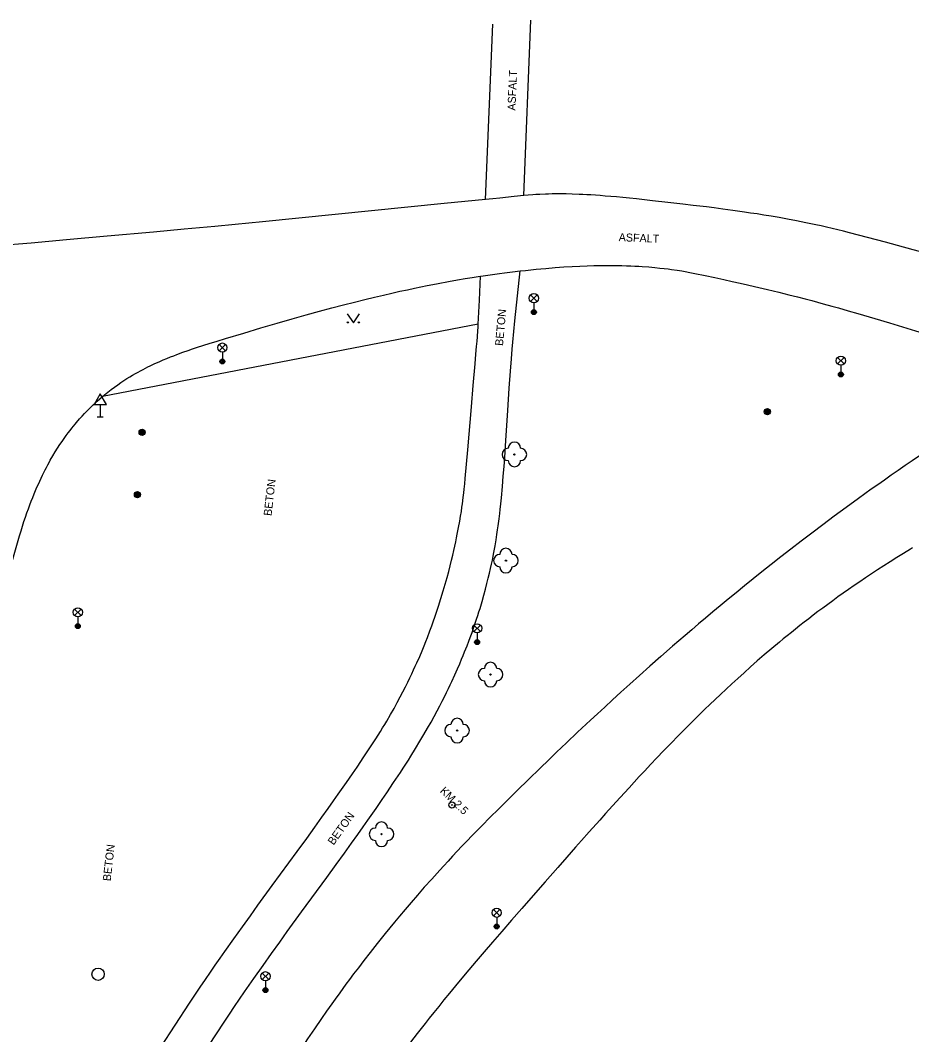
# Model space of a CAD drawing. Extents: x -541281 to -539153, y -1183881 to -1182141.
# Drawn here: x -539853.2 to -539780.8, y -1183251.4 to -1183169.1 of the extents above; entities that cross this region are included whole.
import ezdxf

# ---------------------------------------------------------------- set-up
doc = ezdxf.new("R2010")
doc.units = 0
for name, color, linetype in [('Vrstva 10', 7, 'Continuous'), ('Vrstva 11', 7, 'Continuous'), ('Vrstva 13', 7, 'Continuous'), ('Vrstva 22', 7, 'Continuous'), ('Vrstva 25', 7, 'Continuous'), ('Vrstva 27', 7, 'Continuous'), ('Vrstva 33', 7, 'Continuous'), ('Vrstva 34', 7, 'Continuous'), ('Vrstva 36', 7, 'Continuous'), ('Vrstva 40', 7, 'Continuous')]:
    doc.layers.add(name, color=color, linetype=linetype)

msp = doc.modelspace()

# ---------------------------------------------------------------- linework, layer by layer
at = {"layer": 'Vrstva 10'}
for p, q in [((-539818.798, -1183183.975), (-539830.587, -1183185.158)), ((-539815.43, -1183183.64), (-539818.798, -1183183.975)), ((-539795.35, -1183184.53), (-539796.163, -1183184.42)), ((-539852.324, -1183187.172), (-539857.371, -1183187.609)), ((-539849.441, -1183186.921), (-539852.324, -1183187.172)), ((-539813.254, -1183189.513), (-539812.62, -1183189.44)), ((-539786, -1183192.67), (-539785.21, -1183192.9)), ((-539792.209, -1183220.104), (-539792.806, -1183220.612)), ((-539799.777, -1183227.166), (-539800.402, -1183227.806)), ((-539814.125, -1183243.071), (-539814.863, -1183243.926)), ((-539820.984, -1183251.348), (-539821.54, -1183252.067))]:
    msp.add_line(p, q, dxfattribs=at)
for points in [[(-539808.407, -1183183.203), (-539808.9, -1183183.192), (-539809.331, -1183183.188), (-539809.707, -1183183.189), (-539810.037, -1183183.192), (-539810.325, -1183183.198), (-539810.578, -1183183.206), (-539811.019, -1183183.224), (-539811.349, -1183183.242), (-539811.597, -1183183.258), (-539811.969, -1183183.286), (-539812.34, -1183183.32), (-539813.113, -1183183.398), (-539814.271, -1183183.521), (-539814.85, -1183183.581), (-539815.43, -1183183.64)], [(-539806.516, -1183183.296), (-539806.881, -1183183.273), (-539807.223, -1183183.253), (-539807.544, -1183183.236), (-539807.844, -1183183.223), (-539808.407, -1183183.203)], [(-539805.713, -1183183.357), (-539806.127, -1183183.324), (-539806.516, -1183183.296)], [(-539796.163, -1183184.42), (-539796.876, -1183184.327), (-539797.5, -1183184.248), (-539798.594, -1183184.114), (-539799.415, -1183184.018), (-539800.647, -1183183.877), (-539801.88, -1183183.74), (-539803.186, -1183183.598), (-539803.758, -1183183.538), (-539804.295, -1183183.484), (-539804.798, -1183183.436), (-539805.27, -1183183.394), (-539805.713, -1183183.357)], [(-539785.88, -1183186.34), (-539786.372, -1183186.214), (-539786.849, -1183186.096), (-539787.312, -1183185.986), (-539787.761, -1183185.882), (-539788.196, -1183185.784), (-539788.619, -1183185.692), (-539789.028, -1183185.606), (-539789.426, -1183185.524), (-539790.196, -1183185.372), (-539790.92, -1183185.236), (-539791.6, -1183185.114), (-539792.238, -1183185.005), (-539792.836, -1183184.906), (-539793.398, -1183184.817), (-539793.926, -1183184.736), (-539794.421, -1183184.663), (-539795.35, -1183184.53)], [(-539830.587, -1183185.158), (-539833.534, -1183185.45), (-539835.745, -1183185.665), (-539837.403, -1183185.825), (-539839.891, -1183186.06)], [(-539839.891, -1183186.06), (-539842.38, -1183186.29), (-539846.145, -1183186.629), (-539849.441, -1183186.921)], [(-539782.971, -1183187.108), (-539784.425, -1183186.721), (-539785.88, -1183186.34)], [(-539773.666, -1183189.666), (-539776.712, -1183188.818), (-539778.998, -1183188.187), (-539780.715, -1183187.717), (-539782.004, -1183187.368), (-539782.971, -1183187.108)], [(-539812.62, -1183189.44), (-539812.18, -1183189.392), (-539811.752, -1183189.347), (-539811.338, -1183189.305), (-539810.935, -1183189.267), (-539810.545, -1183189.232), (-539809.787, -1183189.169), (-539809.076, -1183189.117), (-539808.408, -1183189.076), (-539807.781, -1183189.044), (-539807.193, -1183189.021), (-539806.642, -1183189.005), (-539806.125, -1183188.995), (-539805.64, -1183188.99), (-539805.186, -1183188.991), (-539804.761, -1183188.996)], [(-539804.761, -1183188.996), (-539804.362, -1183189.004), (-539803.989, -1183189.015), (-539803.639, -1183189.028), (-539803.311, -1183189.044), (-539803.004, -1183189.061), (-539802.716, -1183189.079), (-539802.177, -1183189.119), (-539801.707, -1183189.16), (-539801.295, -1183189.202), (-539800.936, -1183189.242), (-539800.623, -1183189.281), (-539800.348, -1183189.317), (-539799.869, -1183189.387), (-539799.511, -1183189.443), (-539799.243, -1183189.489), (-539798.841, -1183189.562), (-539798.44, -1183189.64), (-539797.605, -1183189.812), (-539796.823, -1183189.976), (-539796.091, -1183190.134), (-539795.405, -1183190.284)], [(-539823.033, -1183191.24), (-539822.388, -1183191.095), (-539821.782, -1183190.963), (-539821.214, -1183190.842), (-539820.681, -1183190.732), (-539820.181, -1183190.631), (-539819.712, -1183190.538), (-539819.271, -1183190.453), (-539818.445, -1183190.3), (-539817.721, -1183190.171), (-539817.086, -1183190.064), (-539816.53, -1183189.973), (-539816.043, -1183189.896), (-539815.846, -1183189.866), (-539815.617, -1183189.832), (-539814.87, -1183189.724), (-539814.308, -1183189.647), (-539813.887, -1183189.592), (-539813.254, -1183189.513)], [(-539795.405, -1183190.284), (-539794.763, -1183190.428), (-539794.162, -1183190.564), (-539793.599, -1183190.695), (-539792.544, -1183190.945), (-539791.623, -1183191.169), (-539790.818, -1183191.37), (-539790.114, -1183191.549), (-539789.499, -1183191.709), (-539788.962, -1183191.85), (-539788.022, -1183192.103), (-539787.318, -1183192.297), (-539786.79, -1183192.445), (-539786, -1183192.67)], [(-539833.668, -1183194.064), (-539832.361, -1183193.682), (-539831.137, -1183193.331), (-539829.989, -1183193.008), (-539828.913, -1183192.712), (-539827.904, -1183192.442), (-539826.957, -1183192.194), (-539826.069, -1183191.967), (-539825.236, -1183191.76), (-539824.454, -1183191.571)], [(-539824.454, -1183191.571), (-539823.721, -1183191.398), (-539823.033, -1183191.24)], [(-539785.21, -1183192.9), (-539783.839, -1183193.305), (-539782.64, -1183193.661), (-539780.547, -1183194.29), (-539778.979, -1183194.766), (-539777.803, -1183195.126), (-539776.041, -1183195.67)], [(-539842.838, -1183197.23), (-539842.65, -1183197.138), (-539842.284, -1183196.965), (-539841.939, -1183196.81), (-539841.614, -1183196.669), (-539841.307, -1183196.541), (-539841.019, -1183196.425), (-539840.747, -1183196.319), (-539840.491, -1183196.222), (-539840.009, -1183196.045), (-539839.585, -1183195.896), (-539839.212, -1183195.769), (-539838.884, -1183195.66), (-539838.306, -1183195.473), (-539837.87, -1183195.336), (-539837.213, -1183195.132), (-539836.55, -1183194.93), (-539835.062, -1183194.48), (-539833.668, -1183194.064)], [(-539850.169, -1183203.826), (-539849.984, -1183203.542), (-539849.806, -1183203.278), (-539849.635, -1183203.033), (-539849.471, -1183202.805), (-539849.314, -1183202.593), (-539849.163, -1183202.396), (-539849.019, -1183202.213), (-539848.882, -1183202.042), (-539848.751, -1183201.883), (-539848.626, -1183201.735), (-539848.388, -1183201.459), (-539848.173, -1183201.221), (-539847.981, -1183201.015), (-539847.81, -1183200.836), (-539847.658, -1183200.681), (-539847.522, -1183200.546), (-539847.281, -1183200.313), (-539847.096, -1183200.139), (-539846.955, -1183200.011), (-539846.739, -1183199.819), (-539846.52, -1183199.63), (-539846.377, -1183199.51), (-539846.236, -1183199.394), (-539846.097, -1183199.283), (-539845.822, -1183199.068), (-539845.553, -1183198.868), (-539845.292, -1183198.68), (-539845.037, -1183198.504), (-539844.789, -1183198.34), (-539844.548, -1183198.185), (-539844.313, -1183198.039), (-539844.084, -1183197.902), (-539843.862, -1183197.774), (-539843.645, -1183197.652), (-539843.435, -1183197.537), (-539843.23, -1183197.429), (-539843.031, -1183197.327), (-539842.838, -1183197.23)], [(-539852.902, -1183209.788), (-539852.783, -1183209.431), (-539852.664, -1183209.086), (-539852.546, -1183208.755), (-539852.428, -1183208.435), (-539852.311, -1183208.126), (-539852.194, -1183207.829), (-539852.078, -1183207.542), (-539851.963, -1183207.266), (-539851.848, -1183207), (-539851.735, -1183206.744), (-539851.622, -1183206.496), (-539851.51, -1183206.258), (-539851.4, -1183206.028), (-539851.291, -1183205.807), (-539851.182, -1183205.594), (-539851.076, -1183205.388), (-539850.97, -1183205.19), (-539850.866, -1183204.999), (-539850.763, -1183204.815), (-539850.559, -1183204.46), (-539850.361, -1183204.131), (-539850.169, -1183203.826)], [(-539855.674, -1183219.912), (-539855.544, -1183219.349), (-539855.419, -1183218.822), (-539855.298, -1183218.328), (-539855.184, -1183217.865), (-539854.962, -1183216.999), (-539854.763, -1183216.241), (-539854.585, -1183215.579), (-539854.426, -1183214.999), (-539854.143, -1183213.985), (-539853.926, -1183213.224), (-539853.596, -1183212.083), (-539853.26, -1183210.94), (-539853.14, -1183210.542)], [(-539853.14, -1183210.542), (-539853.021, -1183210.158), (-539852.902, -1183209.788)], [(-539780.767, -1183211.929), (-539780.94, -1183212.03), (-539781.504, -1183212.371), (-539782.052, -1183212.709), (-539782.587, -1183213.044), (-539783.108, -1183213.376), (-539783.616, -1183213.704), (-539784.111, -1183214.029), (-539784.594, -1183214.351)], [(-539784.594, -1183214.351), (-539785.065, -1183214.67), (-539785.525, -1183214.985), (-539785.974, -1183215.297), (-539786.411, -1183215.606), (-539786.839, -1183215.912), (-539787.256, -1183216.214), (-539787.664, -1183216.513), (-539788.062, -1183216.808), (-539788.451, -1183217.1), (-539788.832, -1183217.389), (-539789.203, -1183217.675), (-539789.567, -1183217.958), (-539789.922, -1183218.237), (-539790.27, -1183218.513), (-539790.61, -1183218.785), (-539790.943, -1183219.054), (-539791.268, -1183219.321), (-539791.587, -1183219.584), (-539792.209, -1183220.104)], [(-539792.806, -1183220.612), (-539793.378, -1183221.106), (-539793.927, -1183221.589), (-539794.455, -1183222.059), (-539794.961, -1183222.517), (-539795.449, -1183222.963), (-539795.917, -1183223.397), (-539796.368, -1183223.82), (-539796.802, -1183224.232), (-539797.22, -1183224.632), (-539797.623, -1183225.022), (-539798.011, -1183225.401), (-539798.386, -1183225.77), (-539799.107, -1183226.488), (-539799.777, -1183227.166)], [(-539800.402, -1183227.806), (-539800.984, -1183228.41), (-539801.527, -1183228.979)], [(-539801.527, -1183228.979), (-539802.035, -1183229.515), (-539802.509, -1183230.02), (-539802.952, -1183230.496), (-539803.781, -1183231.393), (-539804.503, -1183232.184), (-539805.134, -1183232.88), (-539805.686, -1183233.492), (-539806.169, -1183234.031), (-539807.014, -1183234.978), (-539807.648, -1183235.693), (-539808.125, -1183236.232)], [(-539808.125, -1183236.232), (-539808.841, -1183237.043), (-539809.56, -1183237.86), (-539810.602, -1183239.045), (-539811.576, -1183240.152), (-539812.485, -1183241.189), (-539813.333, -1183242.16), (-539814.125, -1183243.071)], [(-539814.863, -1183243.926), (-539815.552, -1183244.728), (-539816.194, -1183245.482), (-539816.793, -1183246.191), (-539817.352, -1183246.857), (-539817.873, -1183247.483), (-539818.359, -1183248.072), (-539818.813, -1183248.626), (-539819.236, -1183249.147), (-539819.631, -1183249.637), (-539819.999, -1183250.098), (-539820.343, -1183250.532), (-539820.984, -1183251.348)]]:
    msp.add_lwpolyline(points, dxfattribs=at)
at = {"layer": 'Vrstva 11'}
for p, q in [((-539812.34, -1183183.32), (-539811.75, -1183169.09)), ((-539815.43, -1183183.64), (-539814.84, -1183169.41)), ((-539815.938, -1183191.818), (-539815.846, -1183189.866)), ((-539816.03, -1183193.77), (-539846.52, -1183199.63)), ((-539813.508, -1183198.951), (-539813.411, -1183197.587)), ((-539814.186, -1183208.336), (-539814.14, -1183207.85)), ((-539816.269, -1183218.037), (-539816.165, -1183217.724)), ((-539821.575, -1183222.48), (-539821.416, -1183222.148)), ((-539826.312, -1183235.908), (-539825.807, -1183235.198)), ((-539839.46, -1183248.9), (-539839.021, -1183248.235))]:
    msp.add_line(p, q, dxfattribs=at)
for points in [[(-539813.411, -1183197.587), (-539813.332, -1183196.564), (-539813.268, -1183195.798), (-539813.218, -1183195.223), (-539813.137, -1183194.361), (-539813.05, -1183193.5), (-539812.835, -1183191.47), (-539812.62, -1183189.44)], [(-539816.043, -1183194.025), (-539816.03, -1183193.77), (-539815.938, -1183191.818)], [(-539816.878, -1183203.973), (-539816.58, -1183200.482), (-539816.434, -1183198.736), (-539816.29, -1183196.99), (-539816.22, -1183196.185), (-539816.164, -1183195.582), (-539816.124, -1183195.129), (-539816.096, -1183194.79), (-539816.059, -1183194.28), (-539816.043, -1183194.025)], [(-539814.14, -1183207.85), (-539814.062, -1183206.953), (-539813.994, -1183206.113), (-539813.934, -1183205.324), (-539813.881, -1183204.585), (-539813.786, -1183203.198), (-539813.629, -1183200.771), (-539813.508, -1183198.951)], [(-539818.193, -1183212.933), (-539818.094, -1183212.522), (-539818.005, -1183212.137), (-539817.925, -1183211.776), (-539817.852, -1183211.437), (-539817.786, -1183211.118), (-539817.726, -1183210.82), (-539817.619, -1183210.259), (-539817.531, -1183209.767), (-539817.459, -1183209.336), (-539817.4, -1183208.958), (-539817.35, -1183208.628), (-539817.309, -1183208.338), (-539817.243, -1183207.83), (-539817.197, -1183207.448), (-539817.164, -1183207.162), (-539817.12, -1183206.731), (-539817.08, -1183206.3), (-539816.878, -1183203.973)], [(-539816.165, -1183217.724), (-539816.066, -1183217.421), (-539815.973, -1183217.126), (-539815.884, -1183216.841), (-539815.719, -1183216.287), (-539815.571, -1183215.767), (-539815.439, -1183215.279), (-539815.32, -1183214.82), (-539815.213, -1183214.389), (-539815.117, -1183213.985), (-539815.031, -1183213.605), (-539814.953, -1183213.249), (-539814.883, -1183212.915), (-539814.82, -1183212.601), (-539814.763, -1183212.306), (-539814.661, -1183211.753), (-539814.577, -1183211.268), (-539814.508, -1183210.843), (-539814.452, -1183210.471), (-539814.405, -1183210.145), (-539814.328, -1183209.573), (-539814.275, -1183209.143), (-539814.238, -1183208.82), (-539814.186, -1183208.336)], [(-539821.416, -1183222.148), (-539821.27, -1183221.835), (-539821.135, -1183221.54), (-539821.011, -1183221.263), (-539820.782, -1183220.741), (-539820.587, -1183220.282), (-539820.42, -1183219.877), (-539820.277, -1183219.522), (-539820.155, -1183219.21), (-539819.946, -1183218.66), (-539819.794, -1183218.246), (-539819.682, -1183217.934), (-539819.518, -1183217.463), (-539819.36, -1183216.99), (-539819.253, -1183216.661), (-539819.051, -1183216.022), (-539818.869, -1183215.423), (-539818.705, -1183214.86), (-539818.557, -1183214.331), (-539818.423, -1183213.835), (-539818.302, -1183213.37), (-539818.193, -1183212.933)], [(-539820.436, -1183227.071), (-539820.137, -1183226.552), (-539819.862, -1183226.063), (-539819.609, -1183225.601), (-539819.375, -1183225.167), (-539819.159, -1183224.758), (-539818.961, -1183224.373), (-539818.777, -1183224.01), (-539818.607, -1183223.668), (-539818.451, -1183223.347), (-539818.306, -1183223.044), (-539818.172, -1183222.76), (-539817.925, -1183222.223), (-539817.714, -1183221.751), (-539817.534, -1183221.335), (-539817.379, -1183220.97), (-539817.246, -1183220.649), (-539817.131, -1183220.366), (-539816.935, -1183219.87), (-539816.792, -1183219.495), (-539816.686, -1183219.213), (-539816.531, -1183218.788), (-539816.38, -1183218.36), (-539816.269, -1183218.037)], [(-539822.136, -1183223.606), (-539821.933, -1183223.208), (-539821.747, -1183222.833), (-539821.575, -1183222.48)], [(-539827.387, -1183231.93), (-539826.721, -1183230.976), (-539826.225, -1183230.257), (-539825.856, -1183229.715), (-539825.305, -1183228.9), (-539824.76, -1183228.08), (-539824.548, -1183227.756), (-539824.345, -1183227.44), (-539824.151, -1183227.134), (-539823.965, -1183226.835), (-539823.787, -1183226.545), (-539823.616, -1183226.263), (-539823.453, -1183225.989), (-539823.143, -1183225.455), (-539822.858, -1183224.952), (-539822.597, -1183224.476), (-539822.357, -1183224.028), (-539822.136, -1183223.606)], [(-539825.807, -1183235.198), (-539825.366, -1183234.576), (-539824.982, -1183234.03), (-539824.314, -1183233.071), (-539823.817, -1183232.349), (-539823.447, -1183231.805), (-539822.896, -1183230.985), (-539822.35, -1183230.16), (-539822.123, -1183229.812), (-539821.905, -1183229.474), (-539821.696, -1183229.146), (-539821.496, -1183228.827), (-539821.113, -1183228.207), (-539820.76, -1183227.622), (-539820.436, -1183227.071)], [(-539828.209, -1183233.092), (-539827.77, -1183232.473), (-539827.387, -1183231.93)], [(-539833.907, -1183240.938), (-539832.748, -1183239.348), (-539830.715, -1183236.566), (-539829.954, -1183235.52), (-539829.291, -1183234.603), (-539828.713, -1183233.798), (-539828.209, -1183233.092)], [(-539827.559, -1183237.637), (-539826.893, -1183236.716), (-539826.312, -1183235.908)], [(-539832.801, -1183244.847), (-539832.145, -1183243.934), (-539831.527, -1183243.08), (-539830.364, -1183241.482), (-539828.323, -1183238.687), (-539827.559, -1183237.637)], [(-539839.021, -1183248.235), (-539838.593, -1183247.594), (-539838.175, -1183246.976), (-539837.767, -1183246.378), (-539837.37, -1183245.802), (-539836.982, -1183245.245), (-539836.605, -1183244.706), (-539835.87, -1183243.667), (-539835.176, -1183242.695), (-539834.522, -1183241.787), (-539833.907, -1183240.938)], [(-539834.233, -1183246.872), (-539833.497, -1183245.825), (-539832.801, -1183244.847)], [(-539839.117, -1183254.196), (-539837.886, -1183252.313), (-539836.65, -1183250.43), (-539836.222, -1183249.783), (-539835.804, -1183249.159), (-539835.396, -1183248.557), (-539834.998, -1183247.975), (-539834.611, -1183247.414), (-539834.233, -1183246.872)], [(-539844.807, -1183257.195), (-539844.147, -1183256.153), (-539843.568, -1183255.242), (-539842.549, -1183253.652), (-539841.781, -1183252.461), (-539840.623, -1183250.679), (-539839.46, -1183248.9)]]:
    msp.add_lwpolyline(points, dxfattribs=at)
at = {"layer": 'Vrstva 13'}
msp.add_line((-539802.936, -1183222.28), (-539803.716, -1183222.981), dxfattribs=at)
for points in [[(-539778.983, -1183203.634), (-539779.599, -1183204.044), (-539780.204, -1183204.45), (-539780.797, -1183204.851), (-539781.38, -1183205.248), (-539781.951, -1183205.641), (-539782.512, -1183206.03), (-539783.062, -1183206.414), (-539783.602, -1183206.794), (-539784.132, -1183207.17), (-539784.653, -1183207.542), (-539785.164, -1183207.91), (-539786.166, -1183208.638), (-539787.132, -1183209.349)], [(-539787.132, -1183209.349), (-539788.063, -1183210.043), (-539788.961, -1183210.72), (-539789.827, -1183211.381), (-539790.663, -1183212.025), (-539791.469, -1183212.654), (-539792.246, -1183213.266), (-539792.997, -1183213.863), (-539793.722, -1183214.444), (-539794.422, -1183215.01)], [(-539794.422, -1183215.01), (-539795.097, -1183215.561), (-539795.75, -1183216.098)], [(-539795.75, -1183216.098), (-539796.38, -1183216.62), (-539796.989, -1183217.128), (-539797.577, -1183217.622), (-539798.145, -1183218.103), (-539798.695, -1183218.571), (-539799.226, -1183219.026), (-539800.25, -1183219.912), (-539801.207, -1183220.748), (-539802.101, -1183221.536), (-539802.936, -1183222.28)], [(-539803.716, -1183222.981), (-539804.445, -1183223.641), (-539805.126, -1183224.263), (-539805.764, -1183224.848), (-539806.36, -1183225.399)], [(-539806.36, -1183225.399), (-539806.918, -1183225.918), (-539807.961, -1183226.895), (-539808.87, -1183227.754), (-539809.663, -1183228.51), (-539810.355, -1183229.175), (-539810.96, -1183229.758), (-539812.015, -1183230.785), (-539812.804, -1183231.558), (-539813.394, -1183232.141)], [(-539813.394, -1183232.141), (-539814.278, -1183233.018), (-539815.16, -1183233.9), (-539815.632, -1183234.376), (-539816.086, -1183234.838), (-539816.522, -1183235.287), (-539816.943, -1183235.723), (-539817.348, -1183236.148), (-539817.738, -1183236.56), (-539818.113, -1183236.96), (-539818.475, -1183237.349), (-539818.823, -1183237.727), (-539819.159, -1183238.094), (-539819.805, -1183238.809)], [(-539819.805, -1183238.809), (-539820.405, -1183239.483), (-539820.962, -1183240.118)], [(-539820.962, -1183240.118), (-539821.479, -1183240.717), (-539821.961, -1183241.281), (-539822.409, -1183241.813), (-539822.826, -1183242.313), (-539823.214, -1183242.785), (-539823.576, -1183243.229), (-539823.913, -1183243.647), (-539824.228, -1183244.04), (-539824.813, -1183244.782), (-539825.32, -1183245.436), (-539825.76, -1183246.012), (-539826.143, -1183246.518), (-539826.475, -1183246.963), (-539826.765, -1183247.354)], [(-539826.765, -1183247.354), (-539827.268, -1183248.043), (-539827.642, -1183248.563)], [(-539827.642, -1183248.563), (-539827.921, -1183248.955), (-539828.337, -1183249.545), (-539828.75, -1183250.14), (-539829.327, -1183250.98), (-539829.881, -1183251.795), (-539830.414, -1183252.585), (-539830.927, -1183253.352), (-539831.42, -1183254.096), (-539831.895, -1183254.818), (-539832.352, -1183255.518), (-539832.791, -1183256.198), (-539833.215, -1183256.857)]]:
    msp.add_lwpolyline(points, dxfattribs=at)
at = {"layer": 'Vrstva 22'}
for centre in [(-539813.09, -1183204.34), (-539813.78, -1183212.96), (-539815.03, -1183222.21), (-539817.74, -1183226.76), (-539823.88, -1183235.17)]:
    msp.add_circle(centre, 0.05, dxfattribs=at)
for centre, start, end in [((-539813.59, -1183204.34), 89.99973, 269.99973), ((-539813.09, -1183203.84), 359.99973, 179.99973), ((-539812.59, -1183204.34), 269.99973, 89.99973), ((-539813.09, -1183204.84), 179.99973, 359.99973), ((-539813.78, -1183212.46), 359.99973, 179.99973), ((-539814.28, -1183212.96), 89.99973, 269.99973), ((-539813.28, -1183212.96), 269.99973, 89.99973), ((-539813.78, -1183213.46), 179.99973, 359.99973), ((-539815.03, -1183221.71), 359.99973, 179.99973), ((-539815.53, -1183222.21), 89.99973, 269.99973), ((-539814.53, -1183222.21), 269.99973, 89.99973), ((-539815.03, -1183222.71), 179.99973, 359.99973), ((-539817.74, -1183226.26), 359.99973, 179.99973), ((-539818.24, -1183226.76), 89.99973, 269.99973), ((-539817.24, -1183226.76), 269.99973, 89.99973), ((-539817.74, -1183227.26), 179.99973, 359.99973), ((-539823.88, -1183234.67), 360, 180), ((-539824.38, -1183235.17), 90, 270), ((-539823.38, -1183235.17), 270, 90), ((-539823.88, -1183235.67), 179.99999, 359.99999)]:
    msp.add_arc(centre, 0.5, start, end, dxfattribs=at)
at = {"layer": 'Vrstva 25'}
for centre, radius in [((-539792.56, -1183200.87), 0.25), ((-539792.56, -1183200.87), 0.2), ((-539792.56, -1183200.87), 0.15), ((-539792.56, -1183200.87), 0.1), ((-539792.56, -1183200.87), 0.05), ((-539843.31, -1183202.54), 0.25), ((-539843.31, -1183202.54), 0.2), ((-539843.31, -1183202.54), 0.15), ((-539843.31, -1183202.54), 0.1), ((-539843.31, -1183202.54), 0.05), ((-539843.69, -1183207.6), 0.25), ((-539843.69, -1183207.6), 0.2), ((-539843.69, -1183207.6), 0.15), ((-539843.69, -1183207.6), 0.1), ((-539843.69, -1183207.6), 0.05), ((-539818.16, -1183232.8), 0.25), ((-539818.16, -1183232.8), 0.0303)]:
    msp.add_circle(centre, radius, dxfattribs=at)
at = {"layer": 'Vrstva 27'}
msp.add_circle((-539846.89, -1183246.54), 0.5, dxfattribs=at)
at = {"layer": 'Vrstva 33'}
for p, q in [((-539811.775, -1183191.92), (-539811.245, -1183191.39)), ((-539811.775, -1183191.39), (-539811.245, -1183191.92)), ((-539811.51, -1183192.03), (-539811.51, -1183192.78)), ((-539837.065, -1183195.93), (-539836.535, -1183195.4)), ((-539837.065, -1183195.4), (-539836.535, -1183195.93)), ((-539836.8, -1183196.04), (-539836.8, -1183196.79)), ((-539786.855, -1183196.99), (-539786.325, -1183196.46)), ((-539786.855, -1183196.46), (-539786.325, -1183196.99)), ((-539786.59, -1183197.1), (-539786.59, -1183197.85)), ((-539848.795, -1183217.42), (-539848.265, -1183216.89)), ((-539848.795, -1183216.89), (-539848.265, -1183217.42)), ((-539848.53, -1183217.53), (-539848.53, -1183218.28)), ((-539816.385, -1183218.72), (-539815.855, -1183218.19)), ((-539816.385, -1183218.19), (-539815.855, -1183218.72)), ((-539816.12, -1183218.83), (-539816.12, -1183219.58)), ((-539814.795, -1183241.81), (-539814.265, -1183241.28)), ((-539814.795, -1183241.28), (-539814.265, -1183241.81)), ((-539814.53, -1183241.92), (-539814.53, -1183242.67)), ((-539833.565, -1183246.97), (-539833.035, -1183246.44)), ((-539833.565, -1183246.44), (-539833.035, -1183246.97)), ((-539833.3, -1183247.08), (-539833.3, -1183247.83))]:
    msp.add_line(p, q, dxfattribs=at)
for centre, radius in [((-539811.51, -1183191.655), 0.375), ((-539811.51, -1183192.78), 0.2), ((-539811.51, -1183192.78), 0.145), ((-539811.51, -1183192.78), 0.0876), ((-539836.8, -1183195.665), 0.375), ((-539786.59, -1183196.725), 0.375), ((-539836.8, -1183196.79), 0.2), ((-539836.8, -1183196.79), 0.145), ((-539836.8, -1183196.79), 0.0876), ((-539786.59, -1183197.85), 0.2), ((-539786.59, -1183197.85), 0.145), ((-539786.59, -1183197.85), 0.0876), ((-539848.53, -1183217.155), 0.375), ((-539848.53, -1183218.28), 0.2), ((-539848.53, -1183218.28), 0.145), ((-539848.53, -1183218.28), 0.0876), ((-539816.12, -1183218.455), 0.375), ((-539816.12, -1183219.58), 0.2), ((-539816.12, -1183219.58), 0.145), ((-539816.12, -1183219.58), 0.0876), ((-539814.53, -1183241.545), 0.375), ((-539814.53, -1183242.67), 0.2), ((-539814.53, -1183242.67), 0.145), ((-539814.53, -1183242.67), 0.0876), ((-539833.3, -1183246.705), 0.375), ((-539833.3, -1183247.83), 0.2), ((-539833.3, -1183247.83), 0.145), ((-539833.3, -1183247.83), 0.0876)]:
    msp.add_circle(centre, radius, dxfattribs=at)
at = {"layer": 'Vrstva 34'}
for p, q in [((-539846.71, -1183200.272), (-539846.71, -1183201.29)), ((-539846.96, -1183201.29), (-539846.46, -1183201.29))]:
    msp.add_line(p, q, dxfattribs=at)
msp.add_lwpolyline([(-539847.21, -1183200.272), (-539846.21, -1183200.272), (-539846.71, -1183199.406)], close=True, dxfattribs=at)
at = {"layer": 'Vrstva 36'}
msp.add_lwpolyline([(-539826.666, -1183192.914), (-539826.166, -1183193.664), (-539825.666, -1183192.914)], dxfattribs=at)
for centre in [(-539826.616, -1183193.614), (-539825.717, -1183193.614)]:
    msp.add_circle(centre, 0.05, dxfattribs=at)

# ---------------------------------------------------------------- texts
at = {"layer": 'Vrstva 40'}
for s, rotation, p in [('ASFALT', 87.62578, (-539813.01, -1183176.433)), ('ASFALT', 357.6778, (-539804.636, -1183187.02)), ('BETON', 84.83535, (-539814.022, -1183195.544)), ('BETON', 83.4475, (-539832.811, -1183209.354)), ('KM 2.5', 315.55302, (-539819.181, -1183231.715)), ('BETON', 54.53062, (-539827.771, -1183236.107)), ('BETON', 83.4475, (-539845.867, -1183239.007))]:
    msp.add_text(s, height=0.65, rotation=rotation, dxfattribs=at).set_placement(p)

doc.saveas('drawing.dxf')
